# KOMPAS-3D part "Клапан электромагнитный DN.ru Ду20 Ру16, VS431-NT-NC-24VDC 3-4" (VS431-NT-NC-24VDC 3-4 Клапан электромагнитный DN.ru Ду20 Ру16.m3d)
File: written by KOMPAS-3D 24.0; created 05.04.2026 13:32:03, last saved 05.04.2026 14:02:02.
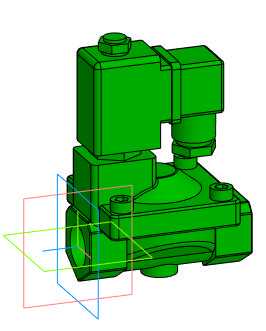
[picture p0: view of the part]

Document properties: Автор: artio; Полное имя файла: C:\Users\artio\OneDrive\Рабочий стол\Клапан электромагнитный DN.ru\VS431\VS431-NT-NC\VS431-NT-NC-24VDC\Ду20\VS431-NT-NC-24VDC 3-4 Клапан электромагнитный DN.ru Ду20 Ру16.m3d

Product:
- Body: Тело 1  | qty 1
    Масса: 1.198355
- Part/product: Клапан электромагнитный DN.ru Ду20 Ру16  | designation VS431-NT-NC-24VDC 3-4
    Масса: 0.907
    Раздел спецификации: Прочие изделия
    Примечание: D130-04748
    additional columns: ef56311e-7521-43dc-8291-0e6108b3d81d; artio; c; Шероховатость не задана; Да

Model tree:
1. Операция без истории:1

Expressions: VS431-NT-NC-24VDC 3-4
